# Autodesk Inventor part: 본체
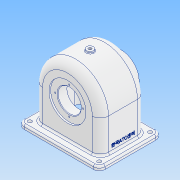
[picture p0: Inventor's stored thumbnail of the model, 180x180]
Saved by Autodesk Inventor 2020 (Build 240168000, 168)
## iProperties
Created: 2022-09
Part Number: 본체
Material: 알루미늄 6061
Document SubType Name: Modeling
Designer: user
Density: 2.7 g/cm^3
Appearance: 알루미늄 - 평지
Mass: 785.009 g
Surface Area: 1042.38 cm^2
Volume: 290.744 cm^3
Author: user
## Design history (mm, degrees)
sketch "스케치1"
  geometry: L1 (-57, 0)-(-57, -57); L2 (57, 0)-(57, -57); L3 (57, -57)-(-57, -57); A1 r 57 centre (0, 0) between (-57, 0) and (57, 0); 1 further point
  constraints: 6 end point, 2 point on circle, 2 vertical, 1 centre point, 1 coincident, 1 perpendicular, 1 tangent
  dimensions: "d0" = 114 diameter of A1; "d1" = 57 distance from line of point (0, 0) L3; "d2" = 114 distance of L2.end L1.end
extrude "돌출1" new body sketch "스케치1" stored distance "d3" = 78; taper "d4" = 0 deg
feature "쉘1" dims "d5" = 5
sketch "스케치2"
  geometry: L1 (5, -73)-(5, -5) reference; L2 (5, -5)-(109, -5) reference; L3 (-13, -93)-(127, -93); L4 (127, -93)-(127, 15); L5 (127, 15)-(-13, 15); L6 (-13, 15)-(-13, -93); 3 further points
  constraints: 8 end point, 2 midpoint, 2 parallel, 1 horizontal, 1 horizontal alignment, 1 perpendicular, 1 vertical alignment
  dimensions: "d6" = 140 distance of L4.end L5.end; "d7" = 108 distance of L5.end L3.start
extrude "돌출2" join sketch "스케치2" distance "d8" = 7; taper "d9" = 0 deg
sketch "스케치3"
  geometry: C1 r 31 at (0, 0); A1 r 57 centre (0, 0) between (57, 0) and (-57, 0) reference
  constraints: 1 centre point, 1 coincident
  dimensions: "d10" = 62 diameter of C1
extrude "돌출3" join sketch "스케치3" distance "d11" = 15; taper "d12" = 0 deg
sketch "스케치4"
  geometry: C1 r 31 at (0, 0) reference; C2 r 20 at (0, 0)
  constraints: 1 centre point, 1 coincident
  dimensions: "d13" = 40 diameter of C2
extrude "돌출4" cut sketch "스케치4" distance "d14" = 16; taper "d15" = 0 deg
sketch "스케치5"
  geometry: L1 (52, 34)-(0, 34) reference; L2 (36.083, 34)-(28, 20); L3 (28, 20)-(0, 20); L4 (0, 20)-(0, 34); 1 further point
  constraints: 6 end point, 1 parallel, 1 perpendicular, 1 point on line
  dimensions: "d16" = 56 diameter of L2.end L4; "d17" = 60 deg angle of L3 L2; "d18" = 14 distance of L3.end L1.end
revolve "회전1" sketch "스케치5" stored, may be unused: angle "d19" = 90 deg
sketch "스케치6"
  geometry: C1 r 28 at (0, 0) reference; C2 r 20 at (0, 0)
  constraints: 1 centre point, 1 coincident
  dimensions: "d20" = 40 diameter of C2
extrude "돌출5" cut sketch "스케치6" distance "d21" = 16; taper "d22" = 0 deg
sketch "스케치7"
  geometry: C1 r 20 at (0, 0) reference; C2 r 32 at (0, 0)
  constraints: 1 centre point, 1 coincident
  dimensions: "d23" = 64 diameter of C2
extrude "돌출6" cut sketch "스케치7" extent not by distance; stored distance "d24" = 75; taper "d25" = 0 deg
sketch "스케치8"
  geometry: C1 r 20 at (0, 0) reference; C2 r 17.5 at (0, 0)
  constraints: 1 centre point, 1 coincident
  dimensions: "d26" = 35 diameter of C2
extrude "돌출7" cut sketch "스케치8" distance "d27" = 16; taper "d28" = 0 deg
node "작업 평면1"
sketch "스케치9"
  geometry: C1 r 6 at (0, 0); 1 further point
  constraints: 1 centre point, 1 coincident
  dimensions: "d30" = 12 diameter of C1
extrude "돌출8" join sketch "스케치9" stored distance "d31" = 16; taper "d32" = 0 deg
sketch "스케치10"
  geometry: C1 r 6 at (0, 0) reference
hole "구멍1" sketch "스케치10" at (0, 0) diameter "d33" = 5.1881; stored, may be unused: countersink angle "d37" = 90 deg, drill point angle "d39" = 118 deg; dims "d34" = 36.75, "d35" = 8, "d36" = 4.4, "d38" = 16
sketch "스케치11" dims "d40" = 48
  geometry: C1 r 20 at (0, 0) reference; C2 r 31 at (0, 0) reference; 5 further points
  constraints: 2 vertical alignment, 1 coincident, 7 other
  dimensions: "d43" = 360 deg dimension on C1.centre point (0, 24) (derived)
hole "구멍2" sketch "스케치11" at (0, 24), (-24, 0), (0, -24), (24, 0) diameter "d45" = 2.459; stored, may be unused: countersink angle "d49" = 90 deg, drill point angle "d51" = 118 deg; dims "d46" = 7, "d47" = 8, "d48" = 4.4, "d50" = 9
sketch "스케치12"
  geometry: C1 r 20 at (0, 0) reference; C2 r 32 at (0, 0) reference; C3 r 24 at (0, 0); C4 r 1.23 at (0, 24) reference; 7 further points
  constraints: 5 coincident, 1 centre point, 9 other
  dimensions: "d52" = 48 diameter of C3; "d55" = 360 deg dimension on C1.centre C4.centre (derived)
hole "구멍3" sketch "스케치12" at (0, 24), (-24, 0), (0, -24), (24, 0) diameter "d57" = 2.459; stored, may be unused: countersink angle "d61" = 90 deg, drill point angle "d63" = 118 deg; dims "d58" = 7, "d59" = 8, "d60" = 4.4, "d62" = 9
fillet "모깎기4" dims "d74" = 3
chamfer "모따기1" distance "d77" = 1; stored, may be unused: second distance "d78" = 2, angle "d79" = 45 deg
node "작업 평면2"
fillet "모깎기6" dims "d84" = 14
sketch "스케치17"
  geometry: L1 (0, -64)-(114, -64) reference; L2 (88.072, -64)-(86.313, -64); L3 (86.313, -64)-(86.313, -73.59); L4 (86.313, -73.59)-(88.072, -73.59); L5 (88.072, -73.59)-(88.072, -64); L6 (109, -5)-(109, -73) reference; L7 (114, -64)-(114, -14) reference; L8 (5, -5)-(109, -5) reference; L9 (14, 0)-(100, 0) reference; L10 (5, -73)-(5, -5) reference; L11 (0, -64)-(0, -14) reference; L12 (109, -73)-(5, -73) reference; L13 (100, -78)-(14, -78) reference; C1 r 2.594 at (57, -39) reference; 2 further points
  constraints: 8 end point, 2 parallel, 1 horizontal, 1 perpendicular, 1 point on line
extrude "돌출9" cut sketch "스케치17" distance "d85" = 7; taper "d86" = 0 deg
sketch "스케치18"
  geometry: L1 (109, -64)-(5, -64) reference; L2 (109, -73)-(5, -73) reference; L3 (109, -64)-(109, -73) reference; L4 (5, -73)-(5, -64) reference; A1 r 14 centre (14, -64) between (0, -64) and (14, -78) reference; 1 further point
extrude "돌출10" cut sketch "스케치18" distance "d87" = 7; taper "d88" = 0 deg
fillet "모깎기7" dims "d89" = 9
fillet "모깎기8" dims "d90" = 10
sketch "스케치19"
  geometry: A1 r 10 centre (-3, 83) between (-3, 93) and (-13, 83) reference; A2 r 10 centre (-3, -5) between (-13, -5) and (-3, -15) reference; A3 r 10 centre (117, -5) between (117, -15) and (127, -5) reference; A4 r 10 centre (117, 83) between (127, 83) and (117, 93) reference; 1 further point
hole "구멍5" sketch "스케치19" at (117, -5), (117, 83), (-3, 83), (-3, -5) diameter "d91" = 6.6; stored, may be unused: countersink angle "d95" = 90 deg, drill point angle "d97" = 118 deg; dims "d92" = 7, "d93" = 8, "d94" = 4.4, "d96" = 9
fillet "모깎기9" dims "d98" = 3, "d99" = 1
sketch "스케치20"
  geometry: L1 (-14, 0)-(-14, -54) reference; L2 (-19, -64)-(-29, -64) reference; 2 further points
  constraints: 1 other
  dimensions: "d100" = 39 distance from line of point (25, -47) L1; "d101" = 17 distance from line of L2 point (25, -47)
feature "엠보싱2" sketch "스케치20" dims "d0" = 114, "d1" = 57, "d2" = 114, "d102" = 0.5, "d103" = 0
fillet "모깎기10" dims "d104" = 0.6
node "솔리드1"
feature "A9D066F2-1C7D-4E18-AEED-F7BC21143FA4" dims "d45" = 2.459, "d46" = 7, "d47" = 8, "d48" = 4.4, "d49" = 90 deg, "d50" = 9, "d51" = 118 deg
